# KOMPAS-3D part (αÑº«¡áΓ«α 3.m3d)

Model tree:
1. Эскиз:1
2. Операция выдавливания:1
     Толщина стенки 1 = 2; Толщина стенки 2 = 8; Расстояние 1 = 1
3. Эскиз:3
4. Операция выдавливания:2
     Толщина стенки 1 = 2; Толщина стенки 2 = 6; Расстояние 1 = 5.5
5. Эскиз:4
6. Операция выдавливания:3
     Толщина стенки 1 = 2; Толщина стенки 2 = 6; Расстояние 1 = 1
7. Эскиз:5
8. Эскиз:6
9. Операция выдавливания:4
     Толщина стенки 1 = 2; Толщина стенки 2 = 2.5; Расстояние 1 = 50
10. Эскиз:7
11. Вырезать элемент выдавливания:1
     Толщина стенки 2 = 1.5; Расстояние 1 = 40
12. Эскиз:8
13. Операция выдавливания:5
     Толщина стенки 1 = 2; Толщина стенки 2 = 2.5; Расстояние 1 = 50
14. Эскиз:9
15. Вырезать элемент выдавливания:2
     Толщина стенки 2 = 1.5; Расстояние 1 = 40
16. Эскиз:10
17. Операция выдавливания:6
     Толщина стенки 1 = 2; Толщина стенки 2 = 2.5; Расстояние 1 = 10
18. Эскиз:11
19. Операция выдавливания:7
     Толщина стенки 1 = 2; Толщина стенки 2 = 6; Расстояние 1 = 1
20. Эскиз:12
21. Операция выдавливания:8
     Толщина стенки 1 = 2; Толщина стенки 2 = 6; Расстояние 1 = 5.5
22. Эскиз:13
23. Операция выдавливания:9
     Толщина стенки 1 = 2; Толщина стенки 2 = 8; Расстояние 1 = 1
24. Эскиз:14
25. Вырезать элемент выдавливания:3
     Толщина стенки 2 = 1.5; Расстояние 1 = 23
26. Эскиз:15
27. Вырезать элемент выдавливания:4
     Толщина стенки 2 = 1.5; Расстояние 1 = 1
28. Эскиз:16
29. Вырезать элемент выдавливания:5
     Расстояние 1 = 150
30. Эскиз:17
31. Операция выдавливания:10
     Толщина стенки 1 = 7; Расстояние 1 = 10; Расстояние 2 = 0.4
